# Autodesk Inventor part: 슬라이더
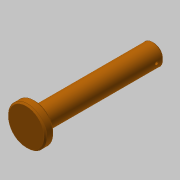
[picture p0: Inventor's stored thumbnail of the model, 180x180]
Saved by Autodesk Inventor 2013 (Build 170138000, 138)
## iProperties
Created: 2019-01
Part Number: 슬라이더
Material: 강철, 연강
Document SubType Name: Modeling
Designer: mduedu
Density: 7.86 g/cm^3
Mass: 120.7 g
Surface Area: 50.2634 cm^2
Volume: 15.3562 cm^3
Author: mduedu
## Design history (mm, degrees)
sketch "스케치1"
  geometry: L1 (0, 0)-(6, 0); L2 (6, 0)-(6, 13); L3 (6, 13)-(0, 13); L4 (0, 13)-(0, 0); L5 (6, 0)-(86, 0); L6 (86, 0)-(86, 7); L7 (86, 7)-(6, 7); L8 (6, 7)-(6, 0)
  constraints: 16 end point, 4 parallel, 2 horizontal, 2 perpendicular
  dimensions: "d0" = 86 distance between parallel lines of L6 L4; "d2" = 6 distance of L2.end L3.end; "d3" = 26 diameter of L3 L1; "d4" = 14 diameter of L7 L5
revolve "회전1" sketch "스케치1" stored, may be unused: angle "d5" = 90 deg
chamfer "모따기1" distance "d6" = 1; stored, may be unused: second distance "d7" = 2, angle "d8" = 45 deg
chamfer "모따기4" distance "d24" = 1; stored, may be unused: second distance "d25" = 2, angle "d28" = 30 deg
sketch "스케치3"
  geometry: L1 (86, 6)-(86, -6) reference; C1 r 1 at (81, 0); 1 further point
  constraints: 1 centre point, 1 horizontal alignment
  dimensions: "d34" = 2 diameter of C1; "d36" = 5 distance from line of C1.centre L1
extrude "돌출1" cut sketch "스케치3" stored distance "d37" = 10; taper "d38" = 0 deg
node "솔리드1"
